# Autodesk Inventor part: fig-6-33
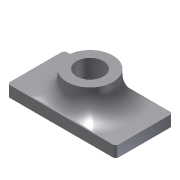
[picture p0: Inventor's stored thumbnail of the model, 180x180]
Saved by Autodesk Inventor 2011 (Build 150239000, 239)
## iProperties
Created: 2004-05
Part Number: fig-6-33
Document SubType Name: Modeling
Designer: CADCIM Technologies
Manufacturer: Standard
Standards Organization: Custom
Density: 1 g/cm^3
Author: CADCIM Technologies
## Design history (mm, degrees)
sketch "Sketch1"
  geometry: L1 (-39.276, -18.692)-(33.721, -18.692); L2 (33.721, -18.692)-(33.721, 19.728); L3 (33.721, 19.728)-(-39.276, 19.728); L4 (-39.276, 19.728)-(-39.276, -18.692)
  constraints: 8 end point, 2 parallel, 1 horizontal, 1 perpendicular
extrude "Extrusion1" new body sketch "Sketch1" distance "d0" = 7.5; taper "d1" = 0 deg
fillet "Fillet1" dims "d2" = 2
sketch "Sketch2"
  geometry: C1 r 15.456 at (-2.778, 0.518)
  constraints: 1 centre point
extrude "Extrusion2" join sketch "Sketch2" distance "d3" = 17.25; taper "d4" = 0 deg
hole "Hole1" diameter "d8" = 18; stored, may be unused: countersink angle "d12" = 90 deg, drill point angle "d14" = 118 deg; dims "d6" = 10, "d7" = 10, "d9" = 6, "d10" = 4, "d11" = 2, "d13" = 8
fillet "Fillet2" dims "d5" = 14
body "Solid1"
